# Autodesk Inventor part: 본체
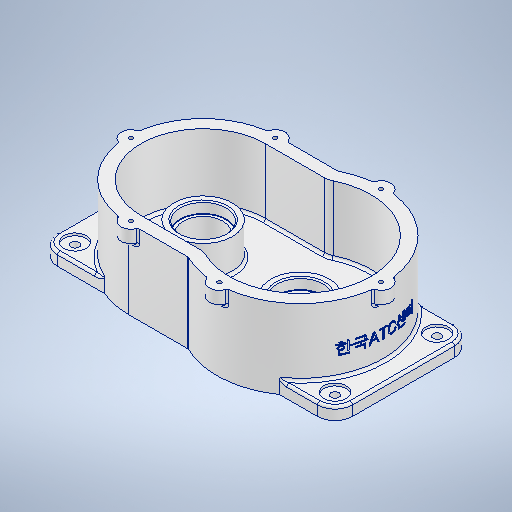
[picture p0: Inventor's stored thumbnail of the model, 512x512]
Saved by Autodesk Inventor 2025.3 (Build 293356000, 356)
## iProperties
Created: 2025-09
Part Number: 본체
Material: 알루미늄 6061
Document SubType Name: Modeling
Designer: PC-15
Mass: 1575.96 g
Surface Area: 1298.41 cm^2
Volume: 583.69 cm^3
Density: 2.7 g/cm^3
Appearance: 알루미늄 - 평지
Author: PC-15
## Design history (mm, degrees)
sketch "스케치1"
  geometry: L1 (118.5, 55)-(-118.5, 55); L2 (-118.5, 55)-(-118.5, -55); L3 (-118.5, -55)-(118.5, -55); L4 (118.5, -55)-(118.5, 55); L5 (118.5, 55)-(-118.5, -55); L6 (-118.5, 55)-(118.5, -55); 1 further point
  constraints: 12 end point, 2 midpoint, 2 parallel, 1 horizontal, 1 perpendicular
  dimensions: "d0" = 237 distance of L3.end L2.end; "d1" = 110 distance of L2.end L1.end
extrude "돌출1" new body sketch "스케치1" distance "d2" = 10; taper "d3" = 0 deg
sketch "스케치2"
  geometry: L1 (-118.5, -55)-(-118.5, 55) reference; L2 (-42.5, 50)-(4.988, 50); L3 (-42.5, -50)-(4.988, -50); L4 (4.988, 60)-(-42.5, 60); L5 (-42.5, -60)-(4.988, -60); L6 (118.5, 55)-(118.5, -55) reference; L7 (-118.5, 55)-(118.5, 55) reference; L8 (-118.5, -55)-(-118.5, 55) reference; L9 (118.5, -55)-(-118.5, -55) reference; A1 r 57 centre (35.5, 0) between (10.654, -51.3) and (10.654, 51.3); A2 r 50 centre (-42.5, 0) between (-42.5, 50) and (-42.5, -50); A3 r 13 centre (4.988, -63) between (10.654, -51.3) and (4.988, -50); A4 r 13 centre (4.988, 63) between (4.988, 50) and (10.654, 51.3); A5 r 3 centre (4.988, 63) between (4.988, 60) and (6.295, 60.3); A6 r 60 centre (-42.5, 0) between (-42.5, 60) and (-42.5, -60); A7 r 3 centre (4.988, -63) between (6.295, -60.3) and (4.988, -60); A8 r 67 centre (35.5, 0) between (6.295, -60.3) and (6.295, 60.3); 7 further points
  constraints: 18 point on circle, 8 centre point, 8 end point, 6 tangent, 2 horizontal, 2 horizontal alignment, 2 point on line, 1 equal radius, 5 other
  dimensions: "d4" = 114 diameter of A1; "d5" = 100 diameter of A2; "d7" = 76 distance from line of L1 A2.centre; "d8" = 78 distance of A1.centre A2.centre; "d9" = 13 radius of A3; "d12" = 10 radial gap between concentric circles of A1 A8
extrude "돌출4" join sketch "스케치2" distance "d15" = 64; taper "d16" = 0 deg
sketch "스케치3"
  geometry: C1 r 23.5 at (35.5, 0); C2 r 23.5 at (-42.5, 0); A1 r 57 centre (35.5, 0) between (10.654, -51.3) and (10.654, 51.3) reference; A2 r 50 centre (-42.5, 0) between (-42.5, 50) and (-42.5, -50) reference; 3 further points
  constraints: 2 centre point, 2 concentric
  dimensions: "d17" = 47 diameter of C1; "d18" = 47 diameter of C2
extrude "돌출5" join sketch "스케치3" distance "d19" = 12; taper "d20" = 0 deg
extrude "돌출6" join sketch "스케치3" distance "d21" = 26; taper "d22" = 0 deg
sketch "스케치4"
  geometry: C1 r 18.5 at (0, 0); C2 r 23.5 at (0, 0) reference; 1 further point
  constraints: 1 centre point, 1 concentric
  dimensions: "d23" = 37 diameter of C1
extrude "돌출7" cut sketch "스케치4" distance "d24" = 9; taper "d25" = 0 deg
sketch "스케치5"
  geometry: C1 r 16 at (0, 0); C2 r 18.5 at (0, 0) reference; 1 further point
  constraints: 1 centre point, 1 concentric
  dimensions: "d26" = 32 diameter of C1
extrude "돌출8" cut sketch "스케치5" distance "d27" = 16; taper "d28" = 0 deg
sketch "스케치6"
  geometry: C1 r 14 at (0, 0); C2 r 16 at (0, 0) reference; 1 further point
  constraints: 1 centre point, 1 concentric
  dimensions: "d29" = 28 diameter of C1
extrude "돌출9" cut sketch "스케치6" distance "d30" = 3; taper "d31" = 0 deg
sketch "스케치7"
  geometry: C1 r 18.5 at (0, 0); C2 r 23.5 at (0, 0) reference; 1 further point
  constraints: 1 centre point, 1 concentric
  dimensions: "d32" = 37 diameter of C1
extrude "돌출10" cut sketch "스케치7" distance "d33" = 9; taper "d34" = 0 deg
sketch "스케치8"
  geometry: C1 r 23.5 at (35.5, 0) reference; C2 r 17.5 at (35.5, 0); 1 further point
  constraints: 1 centre point, 1 coincident
  dimensions: "d35" = 35 diameter of C2
extrude "돌출11" cut sketch "스케치8" distance "d36" = 9.1; taper "d37" = 0 deg
sketch "스케치9"
  geometry: C1 r 15 at (0, 0); C2 r 18.5 at (0, 0) reference; 1 further point
  constraints: 1 centre point, 1 concentric
  dimensions: "d38" = 30 diameter of C1
extrude "돌출12" cut sketch "스케치9" extent not by distance; stored distance "d39" = 9.1; taper "d40" = 0 deg
sketch "스케치10"
  geometry: L1 (-118.5, 55)-(-118.5, -55) reference; L2 (0, 93.8)-(0, -93.8) reference; L3 (-165.9, 0)-(165.9, 0) reference; 5 further points
  constraints: 3 symmetric about line
  dimensions: "d48" = 14 distance from line of L1 point (-104.5, 41); "d49" = 82 distance of point (-104.5, -41) point (-104.5, 41)
hole "구멍1" sketch "스케치10" at (-104.5, 41), (-104.5, -41), (104.5, 41), (104.5, -41) diameter "d41" = 6.6; stored, may be unused: countersink angle "d45" = 90 deg, drill point angle "d47" = 0 deg; dims "d42" = 6, "d43" = 18, "d44" = 2, "d46" = 10
sketch "스케치11"
  geometry: L1 (50.467, -55)-(20.533, -55) reference; L2 (20.533, 55)-(50.467, 55) reference; A1 r 57 centre (35.5, 0) between (20.533, -55) and (50.467, -55) reference; A2 r 57 centre (35.5, 0) between (50.467, 55) and (20.533, 55) reference; 1 further point
extrude "돌출13" join sketch "스케치11" distance "d50" = 10; taper "d51" = 0 deg
sketch "스케치12"
  geometry: L1 (-165.9, 0)-(165.9, 0) reference; C1 r 8 at (-42.5, 58); C2 r 8 at (35.5, 65); C3 r 8 at (35.5, -65); C4 r 8 at (-42.5, -58); C5 r 8 at (-100.5, 0); C6 r 8 at (100.5, 0); C7 r 23.5 at (-42.5, 0) reference; C8 r 23.5 at (35.5, 0) reference; 1 further point
  constraints: 6 centre point, 5 equal radius, 4 vertical alignment, 2 horizontal alignment, 2 other
  dimensions: "d52" = 16 diameter of C1; "d53" = 116 distance of C4.centre C1.centre; "d54" = 130 distance of C3.centre C2.centre; "d55" = 58 distance of C7.centre C5.centre; "d56" = 65 distance of C8.centre C6.centre
extrude "돌출14" join sketch "스케치12" distance "d57" = 12; taper "d58" = 0 deg
sketch "스케치13"
  geometry: L1 (0, 107.408)-(0, -107.408) reference; L2 (-165.9, 0)-(165.9, 0) reference; L3 (-34.754, -60)-(4.988, -60) reference; L4 (4.988, 60)-(-34.754, 60) reference; L5 (4.988, -50)-(-42.5, -50) reference; L6 (-42.5, 50)-(4.988, 50) reference; A1 r 60 centre (-42.5, 0) between (-101.983, -7.861) and (-50.361, -59.483) reference; A2 r 8 centre (-42.5, -58) between (-50.361, -59.483) and (-34.754, -60) reference; A3 r 3 centre (4.988, -63) between (6.295, -60.3) and (4.988, -60) reference; A4 r 67 centre (35.5, 0) between (6.295, -60.3) and (27.649, -66.538) reference; A5 r 8 centre (35.5, -65) between (27.649, -66.538) and (43.351, -66.538) reference; A6 r 67 centre (35.5, 0) between (43.351, -66.538) and (102.038, -7.851) reference; A7 r 8 centre (100.5, 0) between (102.038, -7.851) and (102.038, 7.851) reference; A8 r 67 centre (35.5, 0) between (102.038, 7.851) and (43.351, 66.538) reference; A9 r 8 centre (35.5, 65) between (43.351, 66.538) and (27.649, 66.538) reference; A10 r 67 centre (35.5, 0) between (27.649, 66.538) and (6.295, 60.3) reference; A11 r 3 centre (4.988, 63) between (4.988, 60) and (6.295, 60.3) reference; A12 r 8 centre (-42.5, 58) between (-34.754, 60) and (-50.361, 59.483) reference; A13 r 60 centre (-42.5, 0) between (-50.361, 59.483) and (-101.983, 7.861) reference; A14 r 8 centre (-100.5, 0) between (-101.983, 7.861) and (-101.983, -7.861) reference; A15 r 57 centre (35.5, 0) between (10.654, -51.3) and (10.654, 51.3) reference; A16 r 13 centre (4.988, -63) between (10.654, -51.3) and (4.988, -50) reference; A17 r 50 centre (-42.5, 0) between (-42.5, 50) and (-42.5, -50) reference; A18 r 13 centre (4.988, 63) between (4.988, 50) and (10.654, 51.3) reference; 7 further points
  constraints: 3 coincident, 3 symmetric about line
hole "구멍2" sketch "스케치13" at (35.5, 65), (-42.5, 58), (-100.5, 0), (-42.5, -58), (35.5, -65), (100.5, 0) diameter "d59" = 3.242; stored, may be unused: countersink angle "d63" = 90 deg, drill point angle "d65" = 118 deg; dims "d60" = 8, "d61" = 18, "d62" = 2, "d64" = 10
fillet "모깎기1" dims "d66" = 14
chamfer "모따기2" distance "d70" = 0.3; stored, may be unused: second distance "d71" = 2, angle "d72" = 45 deg
chamfer "모따기3" distance "d73" = 0.8; stored, may be unused: second distance "d74" = 2, angle "d75" = 45 deg
chamfer "모따기4" distance "d76" = 1; stored, may be unused: second distance "d77" = 2, angle "d78" = 45 deg
fillet "모깎기3" dims "d80" = 2
fillet "모깎기4" dims "d81" = 2
fillet "모깎기5" dims "d82" = 2
node "작업 평면1"
sketch "스케치14"
  geometry: L1 (0, 41)-(0, -41) reference; 2 further points
  constraints: 1 horizontal alignment, 1 other
  dimensions: "d84" = 30 distance from line of L1 point (30, 0)
feature "엠보싱1" sketch "스케치14" dims "d0" = 237, "d1" = 110, "d85" = 0.5, "d86" = 0
chamfer "모따기5" distance "d87" = 1; stored, may be unused: second distance "d88" = 2, angle "d89" = 45 deg
node "솔리드1"
node "투영된 루프1"
node "투영된 루프2"
feature "A9D066F2-1C7D-4E18-AEED-F7BC21143FA4" dims "d41" = 6.6, "d42" = 6, "d43" = 18, "d44" = 2, "d45" = 90 deg, "d46" = 10, "d47" = 0
other parameters: "d83" = 169.25
